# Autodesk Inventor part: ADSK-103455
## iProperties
Shininess: 0.0
Created: 2000-03
Part Number: ADSK-103455
Document SubType Name: Modeling
Stock Number: ADSK-103455
Density: 1 g/cm^3
Density: 0.0
Volume: 0.0
Area: 0.0
PropertySet Name: Model Information
Control State: 0
Checked Out: False
Master: False
Author: gao
